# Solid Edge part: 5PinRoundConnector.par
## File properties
Author: conerly
Template: ansi part.par
Last saved by: jccrumbl
Revision: 26
Application: Solid Edge
Density: 0.0979772159 lbm/in^3
Accuracy: 0.990
FromName: Batt(-)
Material: Aluminum, 1060
Face Style: Aluminum
Fill Style: ANSI38(Aluminum)
Virtual Style: Polished aluminum
Coef. of Thermal Exp: 2.3e-05
Thermal Conductivity: 221.0
Specific Heat: 920.0
Modulus of Elasticity: 68947570000.0
Poisson's Ratio: 0.33
Yield Stress: 27579028.0
Ultimate Stress: 68947570.0
Elongation: 0.0
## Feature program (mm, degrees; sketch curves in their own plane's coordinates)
sketch for "unnamed Protrusion 1" plane through (10.8687, 0, 10.8687) normal (0, -1, 0) x-axis (1, 0, 0)
  circle centre (-10.8687, -10.8687) radius 6.35
extrude "unnamed Protrusion 1" add finite 12.7 along -normal
sketch for "ExtrudedCutout_1" #1 plane through (0, 0, 0) normal (0, -1, 0) x-axis (1, 0, 0)
  circle centre (0, 0) radius 0.7937
sketch for "ExtrudedCutout_1" #2 plane through (0, 0, 0) normal (0, -1, 0) x-axis (1, 0, 0)
  circle centre (0, 4.064) radius 0.8599
extrude "ExtrudedCutout_1" cut finite 1.5748 along -normal
pattern "unnamed Pattern 1" of "ExtrudedCutout_1"
extrude "unnamed Cutout 1" cut finite 1.5748
extrude "unnamed Cutout 2" cut finite 1.5748
extrude "unnamed Cutout 3" cut finite 1.5748
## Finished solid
Body 1: solid body, 13 faces, 12 edges, 0 vertices.
  Faces by surface: plane 7, cylinder 6
  Edges by curve: circle 12
Bounding box of the edges (mm): 12.700 x 12.700 x 12.700, from (-6.35, 0, -6.35) to (6.35, 12.7, 6.35).
Cylindrical faces by radius (mm): R0.7937 x1, R0.8599 x4, R6.35 x1
Planar faces by outward normal: +y 1, -y 6
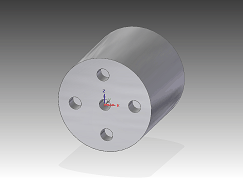
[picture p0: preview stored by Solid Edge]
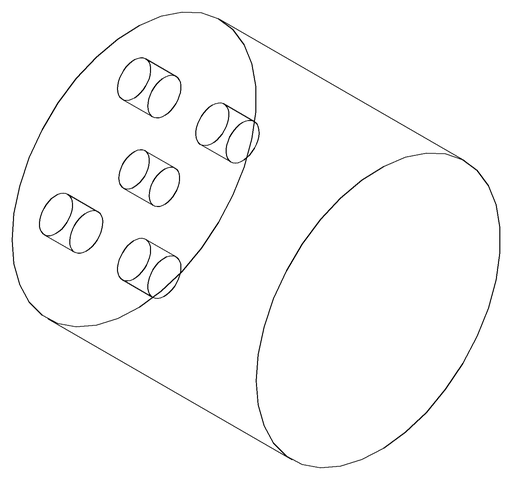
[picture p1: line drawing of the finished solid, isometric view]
